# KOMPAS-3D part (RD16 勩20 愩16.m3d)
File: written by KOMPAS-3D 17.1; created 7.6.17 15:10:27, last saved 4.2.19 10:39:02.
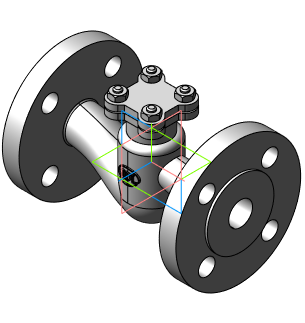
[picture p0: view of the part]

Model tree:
1. Операция без истории:3  (labels: Сталь 20  ГОСТ 1050-88)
